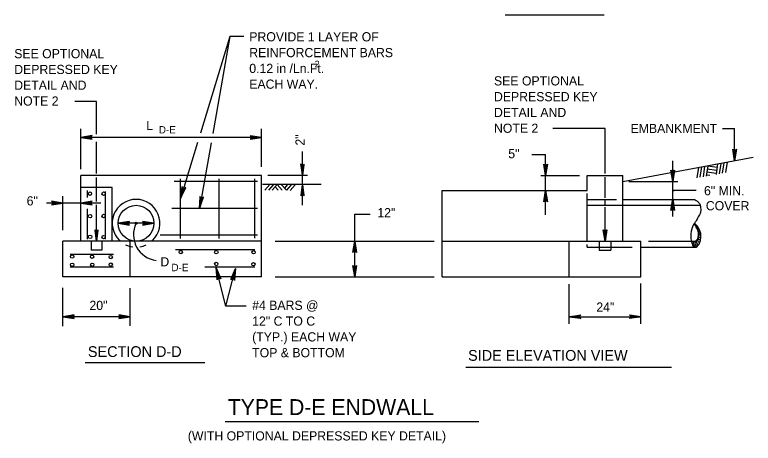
# Model space of a CAD drawing. Extents: x 638877 to 639960, y 297341 to 299123.
# Drawn here: x 639210.4 to 639452, y 298245.5 to 298385.5 of the extents above; entities that cross this region are included whole.
import ezdxf

# ---------------------------------------------------------------- set-up
doc = ezdxf.new("R2010")
doc.units = 0
for name, color, linetype in [('1', 7, 'Continuous'), ('2', 7, 'Continuous'), ('3', 7, 'Continuous')]:
    doc.layers.add(name, color=color, linetype=linetype)

msp = doc.modelspace()

# ---------------------------------------------------------------- linework, layer by layer
at = {"layer": '1'}
for p, q in [((639403.54, 298333.63), (639403.54, 298348.41)), ((639440.37, 298336.8), (639439.86, 298333.39)), ((639441.4, 298336.99), (639440.88, 298333.57)), ((639442.41, 298337.18), (639441.9, 298333.76)), ((639443.44, 298337.37), (639442.92, 298333.95)), ((639434.08, 298335.63), (639433.56, 298332.23)), ((639435.1, 298335.82), (639434.59, 298332.42)), ((639436.12, 298336.01), (639435.61, 298332.61)), ((639437.14, 298336.2), (639436.63, 298332.79)), ((639440.08, 298334.66), (639436.98, 298335.13)), ((639440.23, 298335.63), (639437.13, 298336.1)), ((639440.37, 298336.6), (639439.8, 298336.69)), ((639403.54, 298325.7), (639403.54, 298332.47)), ((639437.83, 298333.01), (639436.69, 298333.18)), ((639439.94, 298333.69), (639436.84, 298334.16)), ((639293.84, 298330.03), (639292.22, 298328.2)), ((639294.99, 298329.99), (639293.41, 298328.2)), ((639296.32, 298330.03), (639294.69, 298328.2)), ((639296.32, 298330.03), (639297.97, 298328.2)), ((639297.64, 298330.03), (639299.29, 298328.2)), ((639299.6, 298329.99), (639298.65, 298328.91)), ((639300.84, 298329.94), (639299.29, 298328.2)), ((639302.2, 298329.99), (639300.58, 298328.15)), ((639295.72, 298329.22), (639296.64, 298328.2)), ((639403.54, 298323.58), (639403.54, 298324.9)), ((639289.89, 298322.25), (639261.79, 298322.25)), ((639403.54, 298311.57), (639403.54, 298322.7))]:
    msp.add_line(p, q, dxfattribs=at)
for centre, radius in [((639235.03, 298327.08), 0.554), ((639239.49, 298327.08), 0.554), ((639235.06, 298319.73), 0.554), ((639239.49, 298319.78), 0.554), ((639250.13, 298317.42), 0.336), ((639235.11, 298312.98), 0.554), ((639239.49, 298312.88), 0.554), ((639264.75, 298307.98), 0.554), ((639276.38, 298307.97), 0.554), ((639288.56, 298307.95), 0.554), ((639229.23, 298306.52), 0.554), ((639235.73, 298306.45), 0.554), ((639241.86, 298306.36), 0.554), ((639229.22, 298303.86), 0.554), ((639235.78, 298303.84), 0.554), ((639241.86, 298303.89), 0.554), ((639276.37, 298304.1), 0.554), ((639288.53, 298304), 0.554)]:
    msp.add_circle(centre, radius, dxfattribs=at)
for centre, radius, start, end in [((639250.13, 298317.42), 7.8, 313.7868, 225.9644), ((639257.81, 298313.71), 8.53, 154.2808, 262.8901), ((639250.13, 298317.42), 7.8, 244.0182, 262.0844), ((639250.13, 298317.42), 7.8, 279.4238, 294.7753)]:
    msp.add_arc(centre, radius, start, end, dxfattribs=at)
at = {"layer": '2'}
for p, q in [((639280.81, 298378.46), (639271.16, 298346.88)), ((639280.81, 298378.46), (639275.23, 298346.73)), ((639285.34, 298378.46), (639280.81, 298378.46)), ((639237.19, 298357.24), (639230.08, 298357.24)), ((639237.19, 298346.58), (639237.19, 298357.24)), ((639232.05, 298335.04), (639232.05, 298348.32)), ((639291.2, 298335.8), (639291.2, 298348.32)), ((639403.54, 298348.41), (639386.5, 298348.41)), ((639441.98, 298348.41), (639445.9, 298348.41)), ((639445.9, 298337.86), (639445.9, 298348.41)), ((639291.2, 298345.44), (639232.05, 298345.44)), ((639237.19, 298333.67), (639237.19, 298344)), ((639270.21, 298343.78), (639264.63, 298325.52)), ((639274.7, 298343.72), (639270.93, 298322.25)), ((639304.56, 298323.27), (639304.56, 298340.86)), ((639379.56, 298339.9), (639384.09, 298339.9)), ((639384.09, 298328.14), (639384.09, 298339.9)), ((639409.39, 298331.07), (639452.02, 298339)), ((639425.67, 298331.07), (639425.67, 298337.83)), ((639232.05, 298311.57), (639232.05, 298333.02)), ((639291.2, 298333.02), (639232.05, 298333.02)), ((639237.19, 298324.57), (639237.19, 298332.41)), ((639264.63, 298312.43), (639264.63, 298331.95)), ((639277.26, 298312.43), (639277.26, 298331.95)), ((639288.99, 298312.58), (639288.99, 298331.95)), ((639291.2, 298299.87), (639291.2, 298333.02)), ((639306.23, 298333.02), (639293.27, 298333.02)), ((639382.49, 298333.02), (639395.19, 298333.02)), ((639397.69, 298333.02), (639409.39, 298333.02)), ((639397.69, 298328.14), (639397.69, 298333.02)), ((639409.39, 298311.57), (639409.39, 298333.02)), ((639289.89, 298331.07), (639262.56, 298331.07)), ((639310.67, 298330.07), (639291.52, 298330.07)), ((639411.29, 298331.07), (639427.34, 298331.07)), ((639425.67, 298325.35), (639425.67, 298331.07)), ((639242.33, 298329.12), (639232.05, 298329.12)), ((639234.25, 298325.86), (639234.25, 298328.12)), ((639240.15, 298312.24), (639240.15, 298327.74)), ((639242.33, 298311.57), (639242.33, 298329.12)), ((639350.24, 298299.87), (639350.24, 298328.14)), ((639350.24, 298328.14), (639397.69, 298328.14)), ((639384.09, 298320.15), (639384.09, 298328.14)), ((639397.69, 298311.57), (639397.69, 298327.18)), ((639425.67, 298328.21), (639433.37, 298328.21)), ((639226.2, 298315.19), (639226.2, 298326.3)), ((639397.69, 298325.22), (639407.3, 298325.22)), ((639409.39, 298325.22), (639432.79, 298325.22)), ((639425.67, 298319.63), (639425.67, 298325.35)), ((639232.05, 298324.03), (639220.86, 298324.03)), ((639238.57, 298324.03), (639232.05, 298324.03)), ((639237.19, 298311.57), (639237.19, 298323.4)), ((639397.69, 298323.27), (639434.53, 298323.27)), ((639234.25, 298312.24), (639234.25, 298322.11)), ((639321.64, 298299.87), (639321.64, 298320.37)), ((639321.64, 298320.37), (639326.74, 298320.37)), ((639255.98, 298317.42), (639244.28, 298317.42)), ((639250.13, 298317.42), (639250.13, 298317.42)), ((639289.89, 298313.56), (639257.96, 298313.56)), ((639232.05, 298311.57), (639226.2, 298311.57)), ((639226.2, 298299.87), (639226.2, 298311.57)), ((639242.33, 298311.57), (639232.05, 298311.57)), ((639235.48, 298311.57), (639235.48, 298308.64)), ((639238.9, 298311.57), (639238.9, 298308.64)), ((639291.2, 298311.57), (639242.33, 298311.57)), ((639248.18, 298299.87), (639248.18, 298311.57)), ((639295.64, 298311.57), (639347.64, 298311.57)), ((639350.24, 298311.57), (639415.24, 298311.57)), ((639391.84, 298299.87), (639391.84, 298311.57)), ((639397.69, 298309.62), (639397.69, 298310.5)), ((639401.59, 298311.57), (639401.59, 298308.64)), ((639405.49, 298311.57), (639405.49, 298308.64)), ((639415.24, 298299.87), (639415.24, 298311.57)), ((639417.75, 298311.57), (639431.77, 298311.57)), ((639238.9, 298308.64), (639235.48, 298308.64)), ((639289.01, 298308.7), (639262.98, 298308.7)), ((639397.69, 298309.62), (639412.4, 298309.62)), ((639401.59, 298308.64), (639405.49, 298308.64)), ((639415.24, 298309.62), (639432.79, 298309.62)), ((639242.72, 298307.2), (639228.57, 298307.2)), ((639242.72, 298303.03), (639228.57, 298303.03)), ((639289.01, 298303.03), (639272.62, 298303.03)), ((639279.52, 298290.29), (639276.3, 298302.86)), ((639279.52, 298290.29), (639282.7, 298302.65)), ((639291.2, 298299.87), (639226.2, 298299.87)), ((639295.64, 298299.87), (639347.64, 298299.87)), ((639350.24, 298299.87), (639415.24, 298299.87)), ((639226.2, 298283.83), (639226.2, 298296.31)), ((639248.18, 298283.93), (639248.18, 298296.25)), ((639391.84, 298284.49), (639391.84, 298297.48)), ((639415.24, 298284.49), (639415.24, 298297.76)), ((639286.1, 298290.29), (639279.52, 298290.29)), ((639248.18, 298286.88), (639226.2, 298286.88)), ((639391.84, 298286.88), (639415.24, 298286.88))]:
    msp.add_line(p, q, dxfattribs=at)
for points in [[(639235.59, 298345.88), (639235.46, 298345.63), (639232.05, 298345.44), (639235.59, 298345.88), (639235.78, 298346.04), (639232.05, 298345.44), (639235.46, 298345.27), (639235.58, 298345.02), (639232.05, 298345.44), (639235.78, 298344.85), (639235.58, 298345.02)], [(639287.66, 298344.99), (639287.79, 298345.25), (639291.2, 298345.44), (639287.66, 298344.99), (639287.48, 298344.84), (639291.2, 298345.44), (639287.8, 298345.61), (639287.67, 298345.86), (639291.2, 298345.44), (639287.48, 298346.03), (639287.67, 298345.86)], [(639446.35, 298341.4), (639446.09, 298341.27), (639445.9, 298337.86), (639446.35, 298341.4), (639446.5, 298341.58), (639445.9, 298337.86), (639445.73, 298341.26), (639445.48, 298341.39), (639445.9, 298337.86), (639445.31, 298341.58), (639445.48, 298341.39)], [(639304.12, 298336.59), (639304.38, 298336.46), (639304.57, 298333.05), (639304.12, 298336.59), (639303.97, 298336.77), (639304.57, 298333.05), (639304.74, 298336.46), (639304.99, 298336.58), (639304.57, 298333.05), (639305.16, 298336.77), (639304.99, 298336.58)], [(639384.53, 298336.56), (639384.27, 298336.42), (639384.09, 298333.02), (639384.53, 298336.56), (639384.69, 298336.74), (639384.09, 298333.02), (639383.92, 298336.42), (639383.67, 298336.55), (639384.09, 298333.02), (639383.49, 298336.74), (639383.67, 298336.55)], [(639426.12, 298334.61), (639425.86, 298334.47), (639425.67, 298331.07), (639426.12, 298334.61), (639426.27, 298334.79), (639425.67, 298331.07), (639425.5, 298334.47), (639425.25, 298334.6), (639425.67, 298331.07), (639425.08, 298334.79), (639425.25, 298334.6)], [(639305.01, 298326.51), (639304.76, 298326.65), (639304.57, 298330.06), (639305.01, 298326.51), (639305.17, 298326.33), (639304.57, 298330.06), (639304.4, 298326.65), (639304.15, 298326.52), (639304.57, 298330.06), (639303.98, 298326.33), (639304.15, 298326.52)], [(639265.26, 298329.21), (639265.48, 298329), (639264.63, 298325.52), (639265.26, 298329.21), (639265.16, 298329.44), (639264.63, 298325.52), (639265.84, 298328.89), (639266.13, 298328.93), (639264.63, 298325.52), (639266.36, 298329.07), (639266.13, 298328.93)], [(639383.64, 298324.6), (639383.9, 298324.73), (639384.09, 298328.14), (639383.64, 298324.6), (639383.49, 298324.41), (639384.09, 298328.14), (639384.26, 298324.73), (639384.51, 298324.61), (639384.09, 298328.14), (639384.68, 298324.41), (639384.51, 298324.61)], [(639271.09, 298325.99), (639271.33, 298325.81), (639270.93, 298322.25), (639271.09, 298325.99), (639270.97, 298326.2), (639270.93, 298322.25), (639271.7, 298325.74), (639271.99, 298325.83), (639270.93, 298322.25), (639272.2, 298325.99), (639271.99, 298325.83)], [(639425.23, 298321.81), (639425.49, 298321.94), (639425.67, 298325.35), (639425.23, 298321.81), (639425.07, 298321.62), (639425.67, 298325.35), (639425.84, 298321.94), (639426.1, 298321.82), (639425.67, 298325.35), (639426.27, 298321.62), (639426.1, 298321.82)], [(639222.66, 298323.58), (639222.79, 298323.84), (639226.2, 298324.03), (639222.66, 298323.58), (639222.48, 298323.43), (639226.2, 298324.03), (639222.8, 298324.2), (639222.67, 298324.45), (639226.2, 298324.03), (639222.48, 298324.62), (639222.67, 298324.45)], [(639235.59, 298324.47), (639235.46, 298324.22), (639232.05, 298324.03), (639235.59, 298324.47), (639235.78, 298324.63), (639232.05, 298324.03), (639235.46, 298323.86), (639235.58, 298323.61), (639232.05, 298324.03), (639235.78, 298323.44), (639235.58, 298323.61)], [(639247.82, 298317.86), (639247.68, 298317.6), (639244.28, 298317.42), (639247.82, 298317.86), (639248, 298318.02), (639244.28, 298317.42), (639247.68, 298317.25), (639247.81, 298316.99), (639244.28, 298317.42), (639248, 298316.82), (639247.81, 298316.99)], [(639252.43, 298316.97), (639252.57, 298317.23), (639255.98, 298317.42), (639252.43, 298316.97), (639252.25, 298316.81), (639255.98, 298317.42), (639252.57, 298317.58), (639252.44, 298317.84), (639255.98, 298317.42), (639252.25, 298318.01), (639252.44, 298317.84)], [(639236.74, 298315.11), (639237, 298314.97), (639237.19, 298311.57), (639236.74, 298315.11), (639236.59, 298315.29), (639237.19, 298311.57), (639237.36, 298314.97), (639237.61, 298315.1), (639237.19, 298311.57), (639237.78, 298315.29), (639237.61, 298315.1)], [(639403.99, 298315.11), (639403.73, 298314.97), (639403.54, 298311.57), (639403.99, 298315.11), (639404.14, 298315.29), (639403.54, 298311.57), (639403.37, 298314.97), (639403.12, 298315.1), (639403.54, 298311.57), (639402.95, 298315.29), (639403.12, 298315.1)], [(639321.2, 298308.02), (639321.46, 298308.16), (639321.64, 298311.57), (639321.2, 298308.02), (639321.04, 298307.84), (639321.64, 298311.57), (639321.81, 298308.16), (639322.06, 298308.03), (639321.64, 298311.57), (639322.24, 298307.84), (639322.06, 298308.03)], [(639322.09, 298303.41), (639321.83, 298303.27), (639321.64, 298299.87), (639322.09, 298303.41), (639322.24, 298303.59), (639321.64, 298299.87), (639321.47, 298303.27), (639321.22, 298303.4), (639321.64, 298299.87), (639321.05, 298303.59), (639321.22, 298303.4)], [(639276.77, 298299.14), (639276.99, 298299.35), (639276.3, 298302.86), (639276.77, 298299.14), (639276.66, 298298.92), (639276.3, 298302.86), (639277.35, 298299.44), (639277.65, 298299.38), (639276.3, 298302.86), (639277.87, 298299.23), (639277.65, 298299.38)], [(639281.32, 298299.18), (639281.62, 298299.24), (639282.7, 298302.65), (639281.32, 298299.18), (639281.12, 298299.03), (639282.7, 298302.65), (639281.98, 298299.16), (639282.2, 298298.96), (639282.7, 298302.65), (639282.33, 298298.72), (639282.2, 298298.96)], [(639229.74, 298287.33), (639229.61, 298287.07), (639226.2, 298286.88), (639229.74, 298287.33), (639229.93, 298287.48), (639226.2, 298286.88), (639229.61, 298286.71), (639229.73, 298286.46), (639226.2, 298286.88), (639229.93, 298286.29), (639229.73, 298286.46)], [(639244.63, 298286.44), (639244.77, 298286.7), (639248.18, 298286.88), (639244.63, 298286.44), (639244.45, 298286.28), (639248.18, 298286.88), (639244.77, 298287.05), (639244.64, 298287.3), (639248.18, 298286.88), (639244.45, 298287.48), (639244.64, 298287.3)], [(639395.38, 298286.44), (639395.25, 298286.7), (639391.84, 298286.88), (639395.38, 298286.44), (639395.57, 298286.28), (639391.84, 298286.88), (639395.25, 298287.05), (639395.37, 298287.3), (639391.84, 298286.88), (639395.57, 298287.48), (639395.37, 298287.3)], [(639411.7, 298287.33), (639411.83, 298287.07), (639415.24, 298286.88), (639411.7, 298287.33), (639411.52, 298287.48), (639415.24, 298286.88), (639411.84, 298286.71), (639411.71, 298286.46), (639415.24, 298286.88), (639411.52, 298286.29), (639411.71, 298286.46)]]:
    msp.add_lwpolyline(points, dxfattribs=at)
msp.add_circle((639250.13, 298317.42), 5.85, dxfattribs=at)
for centre, radius, start, end in [((639433.16, 298316.81), 0.127, 176.947, 93.053), ((639433.26, 298316.68), 0.298, 285.6074, 325.806), ((639433.65, 298316.06), 0.173, 195.7562, 33.8551), ((639433.98, 298315.53), 0.174, 203.3341, 43.8053), ((639434.24, 298314.95), 0.253, 188.5456, 52.8367), ((639434.32, 298314.45), 0.291, 223.7085, 2.3299), ((639434.49, 298313.15), 0.359, 199.7004, 348.5016), ((639434.44, 298313.87), 0.315, 212.411, 346.6825), ((639434.07, 298311.1), 1.67, 168.491, 237.5129), ((639434.06, 298311.08), 1.18, 158.8965, 245.9336), ((639434.56, 298311.46), 1.18, 164.8508, 242.5231), ((639434.41, 298312), 0.667, 173.2089, 278.5784), ((639434.37, 298312.49), 0.415, 171.0795, 335.4873)]:
    msp.add_arc(centre, radius, start, end, dxfattribs=at)
for points in [[(639432.79, 298325.22), (639433.3, 298324.87), (639433.82, 298324.54), (639434.39, 298323.89), (639434.75, 298322.94), (639434.77, 298321.15), (639434.49, 298320.18), (639434.04, 298319.46), (639433.63, 298318.7), (639433.32, 298318.18), (639433.06, 298317.72), (639432.79, 298317.42), (639432.39, 298316.82), (639432.15, 298316.2), (639431.84, 298315.18), (639431.7, 298314.56), (639431.58, 298313.82), (639431.58, 298313.27), (639431.65, 298312.34), (639431.84, 298311.36), (639432.01, 298310.65), (639432.37, 298309.91), (639432.79, 298309.62), (639433.34, 298309.65), (639433.87, 298310.1), (639434.3, 298310.63), (639434.58, 298311.25), (639434.82, 298312.06), (639434.89, 298313.03), (639434.87, 298313.84), (639434.61, 298314.84), (639434.23, 298315.58), (639433.87, 298316.25), (639433.42, 298316.77), (639432.79, 298317.42)], [(639431.77, 298311.57), (639432.25, 298311.53), (639432.87, 298311.58), (639433.2, 298311.63), (639433.46, 298311.87), (639433.65, 298312.06), (639433.85, 298312.37), (639433.99, 298312.79), (639434.08, 298313.25), (639434.11, 298313.75), (639434.11, 298314.18), (639434.01, 298314.63), (639433.92, 298315.06), (639433.75, 298315.37), (639433.44, 298315.91), (639433.34, 298316.18), (639433.25, 298316.41), (639432.99, 298316.82), (639432.87, 298317.11), (639432.79, 298317.42)]]:
    msp.add_spline(points, degree=3, dxfattribs=at)
at = {"layer": '3'}
for p, q in [((639370.84, 298385.54), (639403.25, 298385.54)), ((639233.5, 298271.94), (639272.66, 298271.94)), ((639357.95, 298270.38), (639425.31, 298270.38)), ((639279.32, 298252.63), (639362.23, 298252.63))]:
    msp.add_line(p, q, dxfattribs=at)

# ---------------------------------------------------------------- texts
at = {"layer": '1'}
for s, height, p in [('2', 2.16, (639308.56, 298368.37)), ('D-E', 2.43, (639257.56, 298346.75)), ('D', 3, (639258.08, 298303.32)), ('D-E', 2.43, (639261.69, 298301.74))]:
    msp.add_text(s, height=height, dxfattribs=at).set_placement(p)
msp.add_text('20"', height=3, rotation=360, dxfattribs=at).set_placement((639234.88, 298289.07))
at = {"layer": '2'}
for s, height, p in [('L', 3, (639253.44, 298347.85)), ('.', 3.9, (639425.28, 298327.79))]:
    msp.add_text(s, height=height, dxfattribs=at).set_placement(p)
at = {"layer": '3'}
for s, height, p in [('PROVIDE 1 LAYER OF', 2.9999, (639287.16, 298376.85)), ('SEE OPTIONAL', 2.9999, (639210.27, 298371.34)), ('REINFORCEMENT BARS', 2.9999, (639287.16, 298371.69)), ('DEPRESSED KEY', 2.9999, (639210.27, 298366.18)), ('0.12 in /Ln.Ft.', 2.9999, (639287.16, 298366.53)), ('DETAIL AND', 3, (639210.27, 298361.02)), ('EACH WAY.', 3, (639287.16, 298361.37)), ('SEE OPTIONAL ', 2.9999, (639367.21, 298362.45)), ('NOTE 2', 3, (639210.27, 298355.86)), ('DEPRESSED KEY', 2.9999, (639367.21, 298357.29)), ('DETAIL AND ', 2.9999, (639367.21, 298352.13)), ('NOTE 2', 3, (639367.21, 298346.97)), ('EMBANKMENT', 3, (639411.88, 298346.89)), ('5"', 3, (639371.89, 298338.66)), ('6" MIN.', 3, (639435.92, 298326.56)), ('6"', 3, (639214.34, 298323.23)), ('COVER', 3, (639436.51, 298321.64)), ('12"', 3, (639329.06, 298319.37)), ('#4 BARS @', 3, (639288.11, 298289.1)), ('24"', 3, (639400.69, 298288.52)), ('12" C TO C', 3, (639288.11, 298283.94)), ('(TYP.) EACH WAY', 2.9999, (639288.11, 298278.78)), ('SECTION D-D', 3.5299, (639234.37, 298273.7)), ('TOP & BOTTOM', 2.9999, (639288.11, 298273.62)), ('SIDE ELEVATION VIEW', 3.5299, (639358.74, 298272.46)), ('TYPE D-E ENDWALL', 5.1858, (639280.12, 298254.74)), ('(WITH OPTIONAL DEPRESSED KEY DETAIL)', 2.9999, (639267.05, 298246.42))]:
    msp.add_text(s, height=height, dxfattribs=at).set_placement(p)
msp.add_text('2"', height=3, rotation=90, dxfattribs=at).set_placement((639305.27, 298342.79))

doc.saveas('drawing.dxf')
